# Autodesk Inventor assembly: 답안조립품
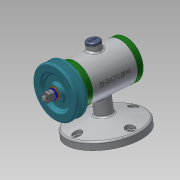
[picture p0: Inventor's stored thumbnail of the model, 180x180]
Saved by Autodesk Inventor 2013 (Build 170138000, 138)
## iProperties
Created: 2018-12
Part Number: 답안조립품
Document SubType Name: Assembly
Designer: Administrator
Author: Administrator
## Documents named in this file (15)
- C:\Users\Administrator\Desktop\481207V1062\답안조립품.iam
- C:\Users\Administrator\Desktop\481207V1062\본체.ipt
- C:\Users\Administrator\Desktop\481207V1062\V벨트풀리.ipt
- C:\Users\Administrator\Desktop\481207V1062\고무캡.ipt
- C:\Users\Administrator\Desktop\481207V1062\너트 M8.ipt
- 너트 M8.ipt
- C:\Users\Administrator\Desktop\481207V1062\뒤커버.ipt
- C:\Users\Administrator\Desktop\481207V1062\베어링 15 x 32 x 9.ipt
- C:\Users\Administrator\Desktop\481207V1062\볼트 M4 x 12.ipt
- C:\Users\Administrator\Desktop\481207V1062\스프링와셔 8.ipt
- C:\Users\Administrator\Desktop\481207V1062\앞커버.ipt
- C:\Users\Administrator\Desktop\481207V1062\오일 실 15 25 7.ipt
- C:\Users\Administrator\Desktop\481207V1062\와셔 8x17.ipt
- C:\Users\Administrator\Desktop\481207V1062\축.ipt
- C:\Users\Administrator\Desktop\481207V1062\키 3 x 3 x 12.ipt
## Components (2 placed, 2 different names)
1. V벨트풀리:1
2. 고무캡:1 — 각도:1
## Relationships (1: Angle 1)
- 각도:1 [Angle]: 고무캡:1
